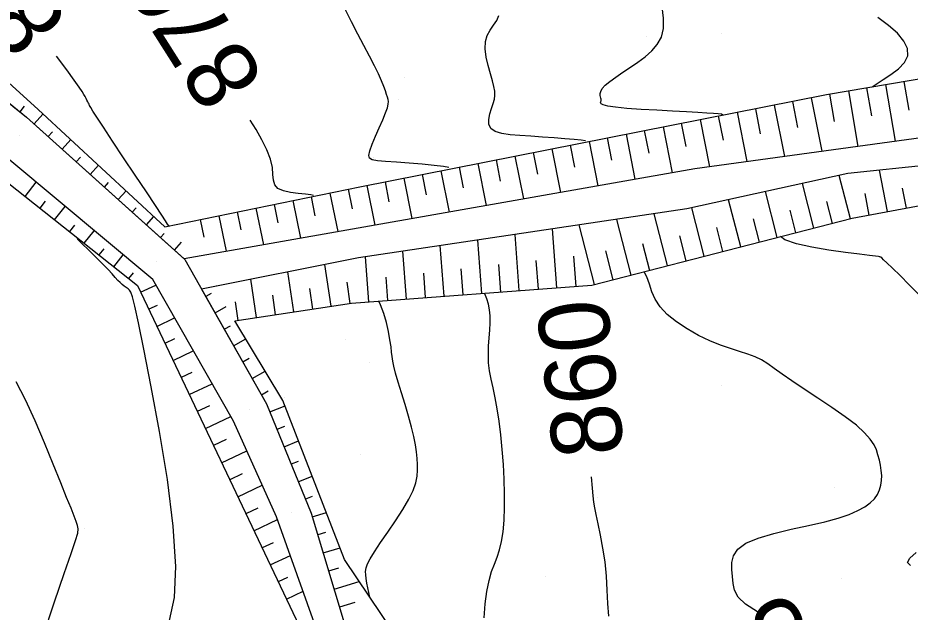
# Model space of a CAD drawing. Extents: x 400243 to 403697, y 4403637 to 4408083.
# Drawn here: x 402859.8 to 402954.4, y 4405995.5 to 4406058.5 of the extents above; entities that cross this region are included whole.
import ezdxf

# ---------------------------------------------------------------- set-up
doc = ezdxf.new("R2010")
doc.units = 0
doc.layers.add('HH_IC', color=7, linetype='Continuous')

msp = doc.modelspace()

# ---------------------------------------------------------------- linework, layer by layer
at = {"layer": 'HH_IC'}
for p, q in [((402817.975, 4406073.406), (402872.494, 4406030.158)), ((402861.986, 4406048.8), (402840.262, 4406068.47)), ((402842.051, 4406063.072), (402860.757, 4406047.989)), ((402847.941, 4406058.366), (402860.757, 4406047.989)), ((402926.477, 4406056.6), (402926.477, 4406056.6)), ((402934.439, 4406056.843), (402934.439, 4406056.843)), ((402945.53, 4406050.391), (402982.46, 4406056.708)), ((402900.831, 4406052.165), (402900.831, 4406052.165)), ((402951.772, 4406051.459), (402952.798, 4406045.456)), ((402954.262, 4406048.762), (402953.743, 4406051.796)), ((402896.065, 4406040.615), (402945.53, 4406050.391)), ((402945.53, 4406050.391), (402945.53, 4406050.391)), ((402946.354, 4406047.542), (402945.857, 4406050.447)), ((402947.829, 4406050.784), (402948.834, 4406044.91)), ((402950.308, 4406048.152), (402949.8, 4406051.121)), ((402900.185, 4406049.86), (402900.185, 4406049.86)), ((402924.498, 4406049.716), (402924.498, 4406049.716)), ((402981.216, 4406049.362), (402931.553, 4406042.535)), ((402942.482, 4406046.896), (402941.932, 4406049.68)), ((402943.894, 4406050.068), (402945.017, 4406044.386)), ((402860.486, 4406049.16), (402860.02, 4406048.583)), ((402861.986, 4406048.8), (402861.986, 4406048.8)), ((402875.41, 4406036.382), (402861.986, 4406048.8)), ((402936.046, 4406048.517), (402937.078, 4406043.294)), ((402938.535, 4406046.236), (402938.008, 4406048.904)), ((402939.97, 4406049.292), (402941.047, 4406043.84)), ((402860.757, 4406047.989), (402877.438, 4406032.993)), ((402860.757, 4406047.989), (402877.53, 4406032.911)), ((402860.757, 4406047.989), (402860.757, 4406047.989)), ((402861.541, 4406047.285), (402862.486, 4406048.337)), ((402932.122, 4406047.741), (402933.108, 4406042.749)), ((402934.588, 4406045.575), (402934.084, 4406048.129)), ((402926.711, 4406044.171), (402926.235, 4406046.578)), ((402928.197, 4406046.965), (402929.157, 4406042.112)), ((402930.643, 4406044.907), (402930.16, 4406047.353)), ((402860.03, 4406046.098), (402860.03, 4406046.098)), ((402863.491, 4406046.463), (402863.028, 4406045.947)), ((402864.515, 4406044.61), (402865.423, 4406045.62)), ((402922.779, 4406043.436), (402922.311, 4406045.802)), ((402924.273, 4406046.19), (402925.217, 4406041.418)), ((402983.304, 4406045.787), (402947.763, 4406042.03)), ((402916.425, 4406044.639), (402917.336, 4406040.028)), ((402918.847, 4406042.701), (402918.387, 4406045.027)), ((402920.349, 4406045.414), (402921.276, 4406040.723)), ((402866.447, 4406043.768), (402866.003, 4406043.273)), ((402897.513, 4406043.772), (402897.513, 4406043.772)), ((402912.501, 4406043.863), (402913.396, 4406039.334)), ((402914.915, 4406041.966), (402914.463, 4406044.251)), ((402874.12, 4406030.788), (402858.965, 4406043.439)), ((402874.12, 4406030.788), (402858.965, 4406043.439)), ((402874.12, 4406030.788), (402858.965, 4406043.439)), ((402867.49, 4406041.936), (402868.36, 4406042.904)), ((402908.577, 4406043.088), (402909.456, 4406038.639)), ((402910.983, 4406041.231), (402910.539, 4406043.476)), ((402931.553, 4406042.535), (402877.438, 4406032.993)), ((402903.118, 4406039.761), (402902.691, 4406041.924)), ((402904.653, 4406042.312), (402905.516, 4406037.944)), ((402907.051, 4406040.496), (402906.615, 4406042.7)), ((402947.763, 4406042.03), (402930.727, 4406038.282)), ((402931.553, 4406042.535), (402931.553, 4406042.535)), ((402948.051, 4406037.236), (402946.871, 4406041.834)), ((402947.763, 4406042.03), (402947.763, 4406042.03)), ((402951.978, 4406037.992), (402951.147, 4406042.388)), ((402860.586, 4406039.604), (402861.77, 4406041.097)), ((402869.403, 4406041.072), (402868.977, 4406040.599)), ((402899.186, 4406039.026), (402898.767, 4406041.149)), ((402900.729, 4406041.537), (402901.576, 4406037.249)), ((402944.176, 4406036.241), (402942.962, 4406040.974)), ((402870.465, 4406039.262), (402871.297, 4406040.187)), ((402875.41, 4406036.382), (402896.065, 4406040.615)), ((402892.885, 4406039.963), (402893.725, 4406035.865)), ((402895.27, 4406038.289), (402894.844, 4406040.365)), ((402896.065, 4406040.615), (402896.065, 4406040.615)), ((402896.805, 4406040.761), (402897.636, 4406036.555)), ((402940.302, 4406035.247), (402939.053, 4406040.114)), ((402949.582, 4406039.899), (402950.013, 4406037.621)), ((402953.543, 4406040.481), (402953.944, 4406038.364)), ((402862.73, 4406039.088), (402862.153, 4406038.362)), ((402888.967, 4406039.16), (402889.784, 4406035.17)), ((402891.34, 4406037.54), (402890.926, 4406039.562)), ((402936.428, 4406034.252), (402935.144, 4406039.254)), ((402945.515, 4406039.071), (402946.114, 4406036.739)), ((402948.249, 4406037.287), (402961.901, 4406039.868)), ((402863.72, 4406037.119), (402864.842, 4406038.533)), ((402872.359, 4406038.377), (402871.952, 4406037.925)), ((402885.048, 4406038.357), (402885.843, 4406034.475)), ((402887.41, 4406036.791), (402887.007, 4406038.759)), ((402930.727, 4406038.282), (402895.917, 4406033.09)), ((402930.727, 4406038.282), (402930.727, 4406038.282)), ((402932.553, 4406033.257), (402931.235, 4406038.394)), ((402941.623, 4406038.144), (402942.239, 4406035.744)), ((402873.44, 4406036.588), (402874.233, 4406037.471)), ((402879.551, 4406035.293), (402879.17, 4406037.153)), ((402881.129, 4406037.554), (402881.903, 4406033.781)), ((402883.481, 4406036.042), (402883.089, 4406037.956)), ((402924.807, 4406031.26), (402923.282, 4406037.171)), ((402928.68, 4406032.26), (402927.259, 4406037.765)), ((402931.352, 4406032.949), (402948.249, 4406037.287)), ((402937.732, 4406037.217), (402938.365, 4406034.749)), ((402948.249, 4406037.287), (402948.249, 4406037.287)), ((402865.832, 4406036.563), (402865.287, 4406035.876)), ((402875.41, 4406036.382), (402875.41, 4406036.382)), ((402916.953, 4406029.911), (402916.486, 4406036.158)), ((402918.926, 4406036.913), (402918.926, 4406036.913)), ((402920.934, 4406030.261), (402919.304, 4406036.578)), ((402933.84, 4406036.289), (402934.491, 4406033.755)), ((402866.854, 4406034.633), (402867.914, 4406035.969)), ((402875.314, 4406035.682), (402874.927, 4406035.251)), ((402912.964, 4406029.613), (402912.519, 4406035.566)), ((402929.932, 4406035.41), (402930.616, 4406032.759)), ((402876.414, 4406033.914), (402877.17, 4406034.755)), ((402904.987, 4406029.015), (402904.585, 4406034.383)), ((402908.976, 4406029.314), (402908.552, 4406034.975)), ((402926.007, 4406034.614), (402926.743, 4406031.76)), ((402868.935, 4406034.038), (402868.421, 4406033.39)), ((402869.988, 4406032.147), (402870.985, 4406033.405)), ((402900.998, 4406028.717), (402900.618, 4406033.791)), ((402922.081, 4406033.818), (402922.87, 4406030.761)), ((402874.567, 4406032.698), (402874.567, 4406032.698)), ((402877.53, 4406032.911), (402886.168, 4406017.605)), ((402877.53, 4406032.911), (402877.53, 4406032.911)), ((402895.917, 4406033.09), (402879.3, 4406029.775)), ((402893.039, 4406027.956), (402892.366, 4406032.382)), ((402895.917, 4406033.09), (402895.917, 4406033.09)), ((402897.009, 4406028.418), (402896.651, 4406033.199)), ((402910.753, 4406032.367), (402910.97, 4406029.463)), ((402914.73, 4406032.812), (402914.959, 4406029.762)), ((402918.708, 4406033.257), (402918.948, 4406030.06)), ((402920.651, 4406030.188), (402931.352, 4406032.949)), ((402931.352, 4406032.949), (402931.352, 4406032.949)), ((402951.148, 4406033.141), (402951.148, 4406033.141)), ((402872.038, 4406031.513), (402871.554, 4406030.904)), ((402889.084, 4406027.355), (402888.439, 4406031.598)), ((402902.797, 4406031.476), (402902.992, 4406028.866)), ((402906.775, 4406031.922), (402906.981, 4406029.165)), ((402874.12, 4406030.788), (402874.12, 4406030.788)), ((402882.666, 4406015.762), (402874.12, 4406030.788)), ((402882.666, 4406015.762), (402874.12, 4406030.788)), ((402882.666, 4406015.762), (402874.12, 4406030.788)), ((402885.13, 4406026.754), (402884.512, 4406030.815)), ((402894.673, 4406030.515), (402895.016, 4406028.256)), ((402898.819, 4406031.031), (402899.003, 4406028.567)), ((402872.494, 4406030.158), (402872.494, 4406030.158)), ((402872.494, 4406030.158), (402894.337, 4405984.152)), ((402872.838, 4406029.435), (402874.453, 4406030.202)), ((402879.3, 4406029.775), (402886.168, 4406017.605)), ((402880.908, 4406030.177), (402880.908, 4406030.177)), ((402890.732, 4406029.823), (402891.061, 4406027.655)), ((402895.179, 4406028.281), (402920.651, 4406030.188)), ((402920.651, 4406030.188), (402920.651, 4406030.188)), ((402880.301, 4406029.308), (402879.742, 4406028.992)), ((402886.791, 4406029.13), (402887.107, 4406027.054)), ((402874.57, 4406028.044), (402873.695, 4406027.629)), ((402880.725, 4406027.25), (402881.896, 4406027.912)), ((402882.812, 4406026.401), (402895.179, 4406028.281)), ((402882.851, 4406028.438), (402883.152, 4406026.453)), ((402895.179, 4406028.281), (402895.179, 4406028.281)), ((402874.553, 4406025.822), (402876.436, 4406026.716)), ((402882.32, 4406025.855), (402881.708, 4406025.509)), ((402887.919, 4406017.973), (402882.812, 4406026.401)), ((402883.152, 4406026.453), (402883.152, 4406026.453)), ((402876.419, 4406024.494), (402875.411, 4406024.015)), ((402882.691, 4406023.767), (402883.97, 4406024.489)), ((402894.504, 4406024.407), (402894.504, 4406024.407)), ((402876.269, 4406022.209), (402878.419, 4406023.229)), ((402884.34, 4406022.401), (402883.673, 4406022.025)), ((402897.124, 4406022.017), (402897.124, 4406022.017)), ((402884.656, 4406020.283), (402886.044, 4406021.067)), ((402920.908, 4406021.727), (402920.908, 4406021.727)), ((402878.268, 4406020.944), (402877.126, 4406020.402)), ((402877.984, 4406018.595), (402880.402, 4406019.743)), ((402934.399, 4406019.553), (402934.399, 4406019.553)), ((402886.36, 4406018.948), (402885.639, 4406018.542)), ((402888.071, 4406018.293), (402888.071, 4406018.293)), ((402880.118, 4406017.394), (402878.842, 4406016.788)), ((402886.168, 4406017.605), (402890.906, 4406006.012)), ((402886.168, 4406017.605), (402890.906, 4406006.012)), ((402886.168, 4406017.605), (402886.168, 4406017.605)), ((402886.518, 4406016.749), (402888.136, 4406017.411)), ((402894.443, 4406001.103), (402887.919, 4406017.973)), ((402879.7, 4406014.982), (402882.385, 4406016.256)), ((402884.354, 4406017.004), (402884.354, 4406017.004)), ((402882.666, 4406015.762), (402882.666, 4406015.762)), ((402887.242, 4406005.626), (402882.666, 4406015.762)), ((402887.242, 4406005.626), (402882.666, 4406015.762)), ((402887.242, 4406005.626), (402882.666, 4406015.762)), ((402888.066, 4406015.221), (402887.274, 4406014.898)), ((402881.907, 4406013.815), (402880.558, 4406013.175)), ((402888.031, 4406013.046), (402889.579, 4406013.679)), ((402881.415, 4406011.368), (402884.079, 4406012.633)), ((402896.105, 4406012.222), (402896.105, 4406012.222)), ((402889.544, 4406011.504), (402888.788, 4406011.195)), ((402883.587, 4406010.186), (402882.273, 4406009.562)), ((402889.544, 4406009.344), (402891.022, 4406009.948)), ((402883.131, 4406007.755), (402885.725, 4406008.986)), ((402946.328, 4406008.721), (402946.328, 4406008.721)), ((402891.022, 4406007.787), (402890.301, 4406007.492)), ((402921.218, 4406007.662), (402921.218, 4406007.662)), ((402885.268, 4406006.556), (402883.989, 4406005.948)), ((402888.771, 4406006.091), (402888.771, 4406006.091)), ((402890.906, 4406006.012), (402896.405, 4405987.776)), ((402890.906, 4406006.012), (402896.405, 4405987.776)), ((402890.906, 4406006.012), (402890.906, 4406006.012)), ((402891.022, 4406005.628), (402892.518, 4406006.08)), ((402884.847, 4406004.141), (402887.348, 4406005.329)), ((402887.242, 4406005.626), (402887.242, 4406005.626)), ((402894.245, 4405985.987), (402887.242, 4406005.626)), ((402894.245, 4405985.987), (402887.242, 4406005.626)), ((402894.245, 4405985.987), (402887.242, 4406005.626)), ((402866.837, 4406004.351), (402866.837, 4406004.351)), ((402892.42, 4406003.961), (402891.599, 4406003.713)), ((402886.864, 4406002.885), (402885.704, 4406002.335)), ((402892.177, 4406001.799), (402893.965, 4406002.338)), ((402886.562, 4406000.528), (402888.698, 4406001.542)), ((402893.797, 4406000.198), (402892.754, 4405999.884)), ((402894.443, 4406001.103), (402894.443, 4406001.103)), ((402909.104, 4405979.306), (402894.443, 4406001.103)), ((402915.694, 4405999.32), (402915.694, 4405999.32)), ((402888.397, 4405999.185), (402887.42, 4405998.721)), ((402893.331, 4405997.969), (402896.008, 4405998.776)), ((402947.109, 4405999.118), (402947.109, 4405999.118)), ((402888.278, 4405996.915), (402890.049, 4405997.755)), ((402892.977, 4405997.094), (402892.977, 4405997.094)), ((402895.542, 4405996.547), (402893.909, 4405996.054))]:
    msp.add_line(p, q, dxfattribs=at)
for points in [[(402905.499, 4406042.669), (402904.923, 4406042.776), (402903.945, 4406042.889), (402902.685, 4406043.007), (402901.301, 4406043.121), (402899.947, 4406043.224), (402898.779, 4406043.308), (402897.922, 4406043.374), (402897.367, 4406043.467), (402897.077, 4406043.639), (402897.009, 4406043.941), (402897.127, 4406044.428), (402897.386, 4406045.128), (402897.737, 4406045.973), (402898.125, 4406046.873), (402898.496, 4406047.735), (402898.798, 4406048.468), (402898.99, 4406049.007), (402899.081, 4406049.382), (402899.094, 4406049.653), (402899.052, 4406049.876), (402898.979, 4406050.11), (402898.889, 4406050.404), (402898.77, 4406050.782), (402898.602, 4406051.262), (402898.365, 4406051.858), (402898.038, 4406052.588), (402897.61, 4406053.462), (402897.091, 4406054.468), (402896.501, 4406055.588), (402895.86, 4406056.803), (402895.187, 4406058.096), (402894.496, 4406059.447)], [(402934.545, 4406048.22), (402934.371, 4406048.317), (402934.041, 4406048.352), (402933.539, 4406048.393), (402932.834, 4406048.442), (402931.891, 4406048.499), (402930.676, 4406048.565), (402929.186, 4406048.642), (402927.54, 4406048.73), (402925.886, 4406048.828), (402924.372, 4406048.936), (402923.149, 4406049.053), (402922.325, 4406049.178), (402921.849, 4406049.306), (402921.63, 4406049.433), (402921.578, 4406049.552), (402921.602, 4406049.66), (402921.626, 4406049.752), (402921.636, 4406049.837), (402921.632, 4406049.925), (402921.614, 4406050.026), (402921.582, 4406050.15), (402921.543, 4406050.306), (402921.531, 4406050.501), (402921.588, 4406050.742), (402921.754, 4406051.034), (402922.069, 4406051.384), (402922.561, 4406051.795), (402923.199, 4406052.259), (402923.937, 4406052.764), (402924.731, 4406053.298), (402925.536, 4406053.849), (402926.308, 4406054.415), (402927.005, 4406055.02), (402927.587, 4406055.7), (402928.014, 4406056.488), (402928.245, 4406057.418), (402928.258, 4406058.507), (402928.091, 4406059.706)], [(402919.959, 4406045.479), (402919.517, 4406045.556), (402918.772, 4406045.637), (402917.788, 4406045.724), (402916.644, 4406045.814), (402915.419, 4406045.9), (402914.191, 4406045.98), (402913.034, 4406046.055), (402911.992, 4406046.146), (402911.104, 4406046.284), (402910.409, 4406046.497), (402909.945, 4406046.813), (402909.732, 4406047.249), (402909.72, 4406047.773), (402909.842, 4406048.342), (402910.027, 4406048.912), (402910.208, 4406049.439), (402910.329, 4406049.896), (402910.378, 4406050.316), (402910.357, 4406050.749), (402910.267, 4406051.246), (402910.109, 4406051.856), (402909.892, 4406052.61), (402909.66, 4406053.466), (402909.463, 4406054.36), (402909.352, 4406055.232), (402909.379, 4406056.02), (402909.573, 4406056.679), (402909.885, 4406057.238), (402910.241, 4406057.742), (402910.57, 4406058.237), (402910.8, 4406058.77)], [(402950.347, 4406051.215), (402951.515, 4406051.98), (402952.334, 4406052.517), (402953.126, 4406053.128), (402953.764, 4406053.799), (402954.122, 4406054.521), (402954.102, 4406055.283), (402953.725, 4406056.076), (402953.039, 4406056.893), (402952.093, 4406057.725), (402950.938, 4406058.564)], [(402875.856, 4406036.493), (402875.83, 4406036.496), (402875.806, 4406036.502), (402875.788, 4406036.51), (402875.767, 4406036.538), (402875.686, 4406036.667), (402875.479, 4406036.995), (402875.075, 4406037.618), (402874.407, 4406038.635), (402873.44, 4406040.094), (402872.272, 4406041.849), (402871.036, 4406043.706), (402869.863, 4406045.47), (402868.886, 4406046.946), (402868.203, 4406047.99), (402867.779, 4406048.654), (402867.546, 4406049.037), (402867.434, 4406049.241), (402867.374, 4406049.366), (402867.31, 4406049.497), (402867.232, 4406049.647), (402867.144, 4406049.814), (402867.048, 4406049.996), (402866.948, 4406050.189), (402866.833, 4406050.405), (402866.65, 4406050.713), (402866.331, 4406051.195), (402865.809, 4406051.933), (402865.017, 4406053.01), (402863.914, 4406054.467)], [(402891.17, 4406039.707), (402890.872, 4406039.769), (402890.3, 4406039.825), (402889.543, 4406039.895), (402888.723, 4406040.005), (402887.96, 4406040.181), (402887.373, 4406040.445), (402887.045, 4406040.821), (402886.909, 4406041.315), (402886.86, 4406041.932), (402886.793, 4406042.677), (402886.603, 4406043.552), (402886.215, 4406044.55), (402885.676, 4406045.616), (402885.065, 4406046.679), (402884.458, 4406047.673)], [(402875.888, 4405994.629), (402876.423, 4405997.074), (402876.582, 4406000.365), (402876.296, 4406004.651), (402875.667, 4406009.576), (402874.843, 4406014.661), (402873.968, 4406019.425), (402873.188, 4406023.389), (402872.618, 4406026.193), (402872.235, 4406027.969), (402871.985, 4406028.97), (402871.813, 4406029.447), (402871.665, 4406029.655), (402871.497, 4406029.805), (402871.305, 4406029.949), (402871.095, 4406030.098), (402870.874, 4406030.265), (402870.649, 4406030.461), (402870.418, 4406030.699), (402870.153, 4406030.998), (402869.818, 4406031.377), (402869.377, 4406031.858), (402868.795, 4406032.46), (402868.063, 4406033.181), (402867.293, 4406033.928), (402866.624, 4406034.587), (402866.193, 4406035.043), (402866.141, 4406035.179), (402866.239, 4406035.12)], [(402955.333, 4406029.158), (402954.283, 4406030.239), (402953.304, 4406031.212), (402952.493, 4406032.001), (402951.921, 4406032.55), (402951.561, 4406032.891), (402951.36, 4406033.074), (402951.267, 4406033.151), (402951.227, 4406033.175), (402951.181, 4406033.189), (402951.038, 4406033.213), (402950.695, 4406033.26), (402950.054, 4406033.343), (402949.015, 4406033.474), (402947.531, 4406033.664), (402945.773, 4406033.914), (402943.966, 4406034.221), (402942.336, 4406034.585), (402941.108, 4406035.003), (402940.643, 4406035.334)], [(402938.185, 4405995.556), (402936.914, 4405996.358), (402936.157, 4405997.115), (402935.775, 4405997.845), (402935.624, 4405998.564), (402935.564, 4405999.291), (402935.497, 4406000.034), (402935.491, 4406000.781), (402935.659, 4406001.509), (402936.111, 4406002.198), (402936.961, 4406002.827), (402938.272, 4406003.381), (402939.929, 4406003.87), (402941.767, 4406004.31), (402943.622, 4406004.717), (402945.331, 4406005.108), (402946.764, 4406005.496), (402947.924, 4406005.888), (402948.849, 4406006.286), (402949.577, 4406006.694), (402950.144, 4406007.115), (402950.584, 4406007.552), (402950.913, 4406008.007), (402951.144, 4406008.479), (402951.288, 4406008.97), (402951.358, 4406009.479), (402951.365, 4406010.007), (402951.321, 4406010.548), (402951.233, 4406011.096), (402951.113, 4406011.644), (402950.968, 4406012.187), (402950.798, 4406012.723), (402950.549, 4406013.277), (402950.155, 4406013.876), (402949.552, 4406014.551), (402948.675, 4406015.331), (402947.49, 4406016.23), (402946.091, 4406017.207), (402944.602, 4406018.204), (402943.149, 4406019.165), (402941.857, 4406020.032), (402940.817, 4406020.763), (402939.985, 4406021.364), (402939.281, 4406021.856), (402938.628, 4406022.261), (402937.946, 4406022.598), (402937.171, 4406022.891), (402936.296, 4406023.172), (402935.329, 4406023.477), (402934.275, 4406023.841), (402933.142, 4406024.297), (402931.948, 4406024.872), (402930.754, 4406025.548), (402929.629, 4406026.295), (402928.644, 4406027.087), (402927.872, 4406027.895), (402927.353, 4406028.696), (402927.015, 4406029.491), (402926.756, 4406030.283), (402926.476, 4406031.078), (402926.204, 4406031.621)], [(402909.224, 4405994.907), (402909.346, 4405996.392), (402909.529, 4405997.729), (402909.762, 4405998.878), (402910.031, 4405999.82), (402910.319, 4406000.618), (402910.604, 4406001.357), (402910.867, 4406002.121), (402911.088, 4406002.997), (402911.249, 4406004.049), (402911.353, 4406005.266), (402911.403, 4406006.62), (402911.404, 4406008.079), (402911.361, 4406009.615), (402911.278, 4406011.194), (402911.159, 4406012.776), (402911.008, 4406014.316), (402910.829, 4406015.77), (402910.625, 4406017.095), (402910.403, 4406018.259), (402910.181, 4406019.288), (402909.978, 4406020.223), (402909.815, 4406021.103), (402909.713, 4406021.966), (402909.683, 4406022.844), (402909.708, 4406023.726), (402909.764, 4406024.594), (402909.823, 4406025.428), (402909.862, 4406026.21), (402909.857, 4406026.925), (402909.802, 4406027.579), (402909.692, 4406028.182), (402909.523, 4406028.746), (402909.291, 4406029.281), (402909.26, 4406029.335)], [(402897.121, 4405997.121), (402896.821, 4405998.587), (402896.741, 4405999.089), (402896.695, 4405999.491), (402896.679, 4405999.844), (402896.724, 4406000.205), (402896.869, 4406000.634), (402897.15, 4406001.19), (402897.605, 4406001.931), (402898.254, 4406002.892), (402899.029, 4406004.014), (402899.846, 4406005.211), (402900.62, 4406006.399), (402901.264, 4406007.493), (402901.715, 4406008.431), (402901.99, 4406009.229), (402902.13, 4406009.929), (402902.175, 4406010.568), (402902.164, 4406011.186), (402902.129, 4406011.822), (402902.063, 4406012.505), (402901.954, 4406013.267), (402901.786, 4406014.138), (402901.546, 4406015.147), (402901.228, 4406016.304), (402900.862, 4406017.543), (402900.486, 4406018.776), (402900.137, 4406019.916), (402899.856, 4406020.877), (402899.667, 4406021.6), (402899.553, 4406022.148), (402899.485, 4406022.613), (402899.432, 4406023.086), (402899.366, 4406023.66), (402899.259, 4406024.401), (402899.103, 4406025.276), (402898.889, 4406026.226), (402898.612, 4406027.193), (402898.265, 4406028.118), (402898.075, 4406028.498)], [(402859.218, 4405980.137), (402860.065, 4405984.37), (402861.199, 4405988.707), (402862.462, 4405992.876), (402863.697, 4405996.607), (402864.747, 4405999.628), (402865.491, 4406001.749), (402865.948, 4406003.103), (402866.175, 4406003.905), (402866.228, 4406004.369), (402866.162, 4406004.711), (402866.021, 4406005.123), (402865.794, 4406005.703), (402865.458, 4406006.53), (402864.991, 4406007.68), (402864.369, 4406009.231), (402863.581, 4406011.213), (402862.665, 4406013.475), (402861.67, 4406015.817), (402860.645, 4406018.04), (402859.641, 4406019.947)], [(402922.444, 4405995.094), (402922.335, 4405996.431), (402922.282, 4405997.864), (402922.207, 4405999.354), (402922.05, 4406000.859), (402921.827, 4406002.323), (402921.574, 4406003.685), (402921.324, 4406004.885), (402921.113, 4406005.862), (402920.965, 4406006.593), (402920.866, 4406007.2), (402920.789, 4406007.841), (402920.71, 4406008.675), (402920.603, 4406009.862)], [(402954.401, 4406000.461), (402954.091, 4406000.798), (402954.334, 4406001.251), (402955.024, 4406001.831)]]:
    msp.add_lwpolyline(points, dxfattribs=at)

# ---------------------------------------------------------------- texts
for s, rotation, p in [('875', 129.74423, (402865.43, 4406058.51)), ('870', 122.39643, (402886.109, 4406052.069)), ('860', 96.46345, (402924.09, 4406012.393)), ('855', 120.65456, (402949.559, 4405983.721))]:
    msp.add_text(s, height=7.5, rotation=rotation, dxfattribs=at).set_placement(p)

doc.saveas('drawing.dxf')
